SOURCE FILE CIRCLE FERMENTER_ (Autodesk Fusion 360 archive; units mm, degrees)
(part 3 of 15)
sketch "Schizzo24" plane through (0, -88.4, 0) normal (0, 1, 0) x axis (-1, 0, 0)
  line L1 (-140.6, 91.5) -> (-140.6, -63.5)
  line L2 (-150.8209, 91.5) -> (-140.6, 91.5)
  line L3 (-150.8209, 41.5) -> (-150.8209, 91.5)
  line L4 (-150.8209, -13.5) -> (-150.8209, 41.5)
  line L5 (-150.8209, -13.5) -> (-150.8209, -63.5)
  line L6 (-140.6, -63.5) -> (-150.8209, -63.5)
  line L7 (-160, -63.5) -> (-85, -63.5)
  line L8 (-160, 91.5) -> (-160, -63.5)
  line L9 (-85, 91.5) -> (-160, 91.5)
  line L10 (0, 91.5) -> (-85, 91.5)
  line L11 (0, 81.5) -> (0, 91.5)
  line L12 (-95, 81.5) -> (0, 81.5)
  curve K1 (-125, 51.5) -> (-95, 81.5)
  line L13 (-125, -23.5) -> (-125, 51.5)
  curve K2 (-125, -23.5) -> (-95, -53.5)
  line L14 (0, -53.5) -> (-95, -53.5)
  line L15 (0, -63.5) -> (0, -53.5)
  line L16 (-85, -63.5) -> (0, -63.5)
  line L17 (-139, 78.5) -> (-139, -14.5)
  circle C1 centre (-139, 76) radius 1.5
  circle C2 centre (-139, 68) radius 1.5
  circle C3 centre (-139, 68) radius 2.5
  circle C4 centre (-139, 76) radius 2.5
  circle C5 centre (-139, -4) radius 1.5
  circle C6 centre (-139, -12) radius 1.5
  circle C7 centre (-139, -4) radius 1.5
  circle C8 centre (-139, -12) radius 1.5
  circle C9 centre (-32, 86.5) radius 3.35
  circle C10 centre (-130, 51.5) radius 3.35
  circle C11 centre (-95, 86.5) radius 3.35
  circle C12 centre (-95, -58.5) radius 3.35
  circle C13 centre (-130, -23.5) radius 3.35
  circle C14 centre (-32, -58.5) radius 3.35
  circle C15 centre (-139, -4) radius 2.5
  circle C16 centre (-139, -12) radius 2.5
  point P36 (-139, -14.5)
  point P37 (-139, 78.5)
  concentric C2 C3
  concentric C1 C4
  concentric C5 C15
  concentric C8 C16
  coincident C16 P36
  coincident C4 P37
  vertical L17
  dimension "d758" diameter C3 = 5
  dimension "d759" diameter C4 = 5
  dimension "d760" diameter C15 = 5
  dimension "d761" diameter C16 = 5
extrude "Estrusione20" add sketch "Schizzo24" profile of L1 C1 C2 C3 C4 C5 C6 C7 C8 C15 C16 L17 to an object
sketch "Schizzo25" plane through (0, -90, 0) normal (0, -1, 0) x axis (1, 0, 0)
  line L1 (160, -63.5) -> (85, -63.5)
  line L2 (160, 91.5) -> (160, -63.5)
  line L3 (85, 91.5) -> (160, 91.5)
  line L4 (0, 91.5) -> (85, 91.5)
  line L5 (0, 81.5) -> (0, 91.5)
  line L6 (95, 81.5) -> (0, 81.5)
  curve K1 (125, 51.5) -> (95, 81.5)
  line L7 (125, -23.5) -> (125, 51.5)
  curve K2 (125, -23.5) -> (95, -53.5)
  line L8 (0, -53.5) -> (95, -53.5)
  line L9 (0, -63.5) -> (0, -53.5)
  line L10 (85, -63.5) -> (0, -63.5)
  curve K3 (139, -2.5) -> (139, -2.5)
  circle C1 centre (139, -4) radius 1.5
  circle C2 centre (139, -12) radius 1.5
  circle C3 centre (32, 86.5) radius 3.35
  circle C4 centre (130, 51.5) radius 3.35
  circle C5 centre (95, 86.5) radius 3.35
  circle C6 centre (95, -58.5) radius 3.35
  circle C7 centre (130, -23.5) radius 3.35
  circle C8 centre (32, -58.5) radius 3.35
  circle C9 centre (139, -12) radius 1.5
extrude "Estrusione21" add sketch "Schizzo25" profile of C1 C2 K3 C9 against normal blind 0.8
work_plane "Piano di lavoro7" AlongDistance -5
sketch "Schizzo26" plane through (0, -85, 0) normal (0, -1, 0) x axis (-1, 0, 0)
  curve K1 (-140.3526, 4.6485) -> (-140.4601, 4.3436)
  circle C1 centre (-139, -76) radius 1.5
  circle C2 centre (-139, -68) radius 1.5
  circle C3 centre (-139, 12) radius 1.5
  circle C4 centre (-139, 4) radius 2.3
  circle C5 centre (-139, 12) radius 2.3
  circle C6 centre (-139, -68) radius 2.3
  circle C7 centre (-139, -76) radius 2.3
  arc A1 centre (-139, 4) radius 1.5 clockwise from (-140.3526, 4.6485) to (-140.4601, 4.3436)
  concentric C3 C5
  concentric C2 C6
  concentric C1 C7
  dimension "d768" diameter C4 = 4.6
  dimension "d769" diameter C5 = 4.6
  dimension "d770" diameter C6 = 4.6
  dimension "d771" diameter C7 = 4.6
extrude "Estrusione22" cut sketch "Schizzo26" profile of C1 C2 C3 C4 C5 C6 C7 against normal blind 5.06
component_insert "Inserimento componente2"
component_insert "Inserimento componente3"
component_insert "Inserimento componente4"
component_insert "Inserimento componente5"
sketch "Schizzo27" plane through (0, -85, 0) normal (0, 1, 0) x axis (-1, 0, 0)
  line L1 (-137.1434, -13.3576) -> (-137.1434, -10.6424)
  line L2 (-137.1434, -5.3576) -> (-137.1434, -2.6424)
  line L3 (-137.1434, 74.6424) -> (-137.1434, 77.3576)
  line L4 (-137.1434, 66.6424) -> (-137.1434, 69.3576)
  arc A1 centre (-139, -12) radius 2.3 clockwise from (-137.1434, -13.3576) to (-137.1434, -10.6424)
  circle C1 centre (-139, -12) radius 1.5
  arc A2 centre (-139, -4) radius 2.3 clockwise from (-137.1434, -5.3576) to (-137.1434, -2.6424)
  circle C2 centre (-139, -4) radius 1.5
  arc A3 centre (-139, 76) radius 2.3 clockwise from (-137.1434, 74.6424) to (-137.1434, 77.3576)
  circle C3 centre (-139, 76) radius 1.5
  arc A4 centre (-139, 68) radius 2.3 clockwise from (-137.1434, 66.6424) to (-137.1434, 69.3576)
  circle C4 centre (-139, 68) radius 1.5
  circle C5 centre (-139, 68) radius 2
  circle C6 centre (-139, 76) radius 2
  circle C7 centre (-139, -4) radius 2
  circle C8 centre (-139, -12) radius 2
  concentric A4 C5
  concentric A3 C6
  concentric A2 C7
  concentric A1 C8
  dimension "d792" diameter C5 = 4
  dimension "d793" diameter C6 = 4
  dimension "d794" diameter C7 = 4
  dimension "d795" diameter C8 = 4
extrude "Estrusione24" cut sketch "Schizzo27" profile of L1 C1 L2 C2 L3 C3 L4 C4 C5 C6 C7 C8 against normal blind 4.2
joint "Assembla2" alignAngle 0 alignOffsetX 0 alignOffsetY 0 alignOffsetZ 0
joint "Assembla3" alignAngle 0 alignOffsetX 0 alignOffsetY 0 alignOffsetZ 0
joint "Assembla4" alignAngle 0 alignOffsetX 0 alignOffsetY 0 alignOffsetZ 0
joint "Assembla5" alignAngle 0 alignOffsetX 0 alignOffsetY 0 alignOffsetZ 0
sketch "Schizzo2" plane through (0, -88.4, 0) normal (0, 1, 0) x axis (-1, 0, 0)
  line L1 (-140.6, 74.0791) -> (-140.6, 69.9209)
  line L2 (-140.6, 91.5) -> (-140.6, 77.9209)
  line L3 (-150.8209, 91.5) -> (-140.6, 91.5)
  line L4 (-150.8209, 41.5) -> (-150.8209, 91.5)
  line L5 (-150.8209, -13.5) -> (-150.8209, 41.5)
  line L6 (-150.8209, -13.5) -> (-150.8209, -63.5)
  line L7 (-140.6, -63.5) -> (-150.8209, -63.5)
  line L8 (-140.6, -13.9209) -> (-140.6, -63.5)
  line L9 (-140.6, -5.9209) -> (-140.6, -10.0791)
  line L10 (-140.6, 66.0791) -> (-140.6, -2.0791)
  arc A1 centre (-139, 68) radius 2.5 clockwise from (-140.6, 66.0791) to (-140.6, 69.9209)
  arc A2 centre (-139, 76) radius 2.5 clockwise from (-140.6, 74.0791) to (-140.6, 77.9209)
  arc A3 centre (-139, -12) radius 2.5 clockwise from (-140.6, -13.9209) to (-140.6, -10.0791)
  arc A4 centre (-139, -4) radius 2.5 clockwise from (-140.6, -5.9209) to (-140.6, -2.0791)
extrude "Estrusione25" add sketch "Schizzo2" to an object
work_plane "Piano di lavoro1" AlongDistance -25
sketch "Schizzo3" plane through (0, 0, 91.5) normal (0, 0, 1) x axis (1, 0, 0)
  curve K1 (150.8209, -88.4) -> (151.0572, -87.4594)
  curve K2 (151.0572, -87.4594) -> (150.8209, -87.3312)
  line L1 (150.8209, -87.3312) -> (150.8209, -88.4)
extrude "Estrusione26" add sketch "Schizzo3" against normal blind 155
sketch "Schizzo4" plane through (0, -90, 0) normal (0, -1, 0) x axis (1, 0, 0)
  line L1 (160, -63.5) -> (85, -63.5)
  line L2 (160, 91.5) -> (160, -63.5)
  line L3 (85, 91.5) -> (160, 91.5)
  line L4 (0, 91.5) -> (85, 91.5)
  line L5 (0, 81.5) -> (0, 91.5)
  line L6 (95, 81.5) -> (0, 81.5)
  curve K1 (125, 51.5) -> (95, 81.5)
  line L7 (125, -23.5) -> (125, 51.5)
  curve K2 (125, -23.5) -> (95, -53.5)
  line L8 (0, -53.5) -> (95, -53.5)
  line L9 (0, -63.5) -> (0, -53.5)
  line L10 (85, -63.5) -> (0, -63.5)
  line L11 (139.6, 91.5) -> (139.6, 78.4269)
  line L12 (140.6, 91.5) -> (139.6, 91.5)
  line L13 (140.6, 77.9209) -> (140.6, 91.5)
  line L14 (139.6, 73.5731) -> (139.6, 70.4269)
  line L15 (140.6, 69.9209) -> (140.6, 74.0791)
  line L16 (140.6, -2.0791) -> (140.6, 66.0791)
  line L17 (139.6, 65.5731) -> (139.6, -1.5731)
  line L18 (140.6, -10.0791) -> (140.6, -5.9209)
  line L19 (139.6, -6.4269) -> (139.6, -9.5731)
  line L20 (140.6, -63.5) -> (140.6, -13.9209)
  line L21 (139.6, -63.5) -> (140.6, -63.5)
  line L22 (139.6, -14.4269) -> (139.6, -63.5)
  circle C1 centre (32, -58.5) radius 3.35
  circle C2 centre (130, -23.5) radius 3.35
  circle C3 centre (95, -58.5) radius 3.35
  circle C4 centre (95, 86.5) radius 3.35
  circle C5 centre (130, 51.5) radius 3.35
  circle C6 centre (32, 86.5) radius 3.35
  arc A1 centre (139, 76) radius 2.5 clockwise from (139.6, 78.4269) to (140.6, 77.9209)
  arc A2 centre (139, 68) radius 2.5 clockwise from (139.6, 70.4269) to (140.6, 69.9209)
  arc A3 centre (139, 76) radius 2.5 clockwise from (140.6, 74.0791) to (139.6, 73.5731)
  arc A4 centre (139, 68) radius 2.5 clockwise from (140.6, 66.0791) to (139.6, 65.5731)
  arc A5 centre (139, -4) radius 2.5 clockwise from (139.6, -1.5731) to (140.6, -2.0791)
  arc A6 centre (139, -4) radius 2.5 clockwise from (140.6, -5.9209) to (139.6, -6.4269)
  arc A7 centre (139, -12) radius 2.5 clockwise from (139.6, -9.5731) to (140.6, -10.0791)
  arc A8 centre (139, -12) radius 2.5 clockwise from (140.6, -13.9209) to (139.6, -14.4269)
extrude "Estrusione27" add sketch "Schizzo4" profile of L1 L3 A1 L11 L12 L13 A2 L14 A3 L15 A4 L16 A5 L17 A6 L18 A7 L19 A8 L20 L21 L22 against normal blind 7
mirror "Specchio2" mirrorStitchTolerance 0.1
mirror "Specchio2" mirrorStitchTolerance 0.1
component_from_bodies "Corpo->Comp1"
base_feature "Lavorazione di base1"
sketch "Schizzo2" plane through (0, 88.4, 0) normal (0, -1, 0) x axis (1, 0, 0)
  line L1 (0, -53.5) -> (95, -53.5)
  line L2 (0, -63.5) -> (0, -53.5)
  line L3 (95, -63.5) -> (0, -63.5)
  curve K1 (95, -63.5) -> (135, -23.5)
  line L4 (135, 51.5) -> (135, -23.5)
  curve K2 (95, 91.5) -> (135, 51.5)
  line L5 (0, 91.5) -> (95, 91.5)
  line L6 (0, 81.5) -> (0, 91.5)
  line L7 (95, 81.5) -> (0, 81.5)
  curve K3 (125, 51.5) -> (95, 81.5)
  line L8 (125, -23.5) -> (125, 51.5)
  curve K4 (125, -23.5) -> (95, -53.5)
  line L9 (95, -63) -> (0, -63)
  curve K5 (95, -63) -> (134.5, -23.5)
  line L10 (134.5, 51.5) -> (134.5, -23.5)
  line L11 (0, 91) -> (0, -63)
  curve K6 (95, 91) -> (134.5, 51.5)
  line L12 (0, 91) -> (95, 91)
  circle C1 centre (32, 86.5) radius 1.75
  circle C2 centre (130, 51.5) radius 1.75
  circle C3 centre (95, 86.5) radius 1.75
  circle C4 centre (95, -58.5) radius 1.75
  circle C5 centre (130, -23.5) radius 1.75
  circle C6 centre (32, -58.5) radius 1.75
  point P26 (0, 91)
  coincident L6 P26
  perpendicular L9 L11
  dimension "d782" = -0.5
  dimension "d785" = -0.5
extrude "Estrusione2" new body sketch "Schizzo2" profile of C1 C2 C3 C4 C5 C6 L1 L2 L6 L7 K3 L8 K4 K5 L9 L10 L11 L12 K6 along normal blind 3
component_from_bodies "Corpo->Comp2"
copy_paste "CopiaIncolla2"
joint "Assembla2" alignAngle 0 alignOffsetX 0 alignOffsetY 0 alignOffsetZ 0
remove_instance "RimuoviIstanza1"
component_from_bodies "Corpo->Comp1"
base_feature "Lavorazione di base1" bodies "PROFILO BASE"
mirror "Specchio1" mirrorStitchTolerance 0.1
mirror "Specchio1" mirrorStitchTolerance 0.1
remove_instance "RimuoviIstanza2"
remove_instance "RimuoviIstanza4"
mirror_component "SpecchiaComponente1"
derived_instance "DerivedInstance1"
mirror_component "SpecchiaComponente2"
derived_instance "DerivedInstance2"
mirror "Specchio1" mirrorStitchTolerance 0.1
mirror_component "SpecchiaComponente3"
derived_instance "DerivedInstance3"
derived_instance "DerivedInstance4"
derived_instance "DerivedInstance5"
derived_instance "DerivedInstance6"
sketch "Schizzo1" plane through (0, -72.4, 0) normal (0, 1, 0) x axis (-1, 0, 0)
  line L1 (142, 64) -> (-142, 64)
  curve K1 (142, 64) -> (143, 65)
  line L2 (143, 79) -> (143, 65)
  curve K2 (143, 79) -> (142, 80)
  line L3 (-142, 80) -> (142, 80)
  curve K3 (-143, 79) -> (-142, 80)
  line L4 (-143, 65) -> (-143, 79)
  curve K4 (-142, 64) -> (-143, 65)
  line L5 (142, 64) -> (-142, 64)
  curve K5 (142, 64) -> (143, 65)
  line L6 (143, 79) -> (143, 65)
  curve K6 (143, 79) -> (142, 80)
  line L7 (-142, 80) -> (142, 80)
  curve K7 (-143, 79) -> (-142, 80)
  line L8 (-143, 65) -> (-143, 79)
  curve K8 (-142, 64) -> (-143, 65)
  circle C1 centre (139, 76) radius 1.75
  circle C2 centre (139, 68) radius 1.75
  circle C3 centre (-139, 68) radius 1.75
  circle C4 centre (-139, 76) radius 1.75
  circle C5 centre (139, 76) radius 1.75
  circle C6 centre (139, 68) radius 1.75
  circle C7 centre (-139, 68) radius 1.75
  circle C8 centre (-139, 76) radius 1.75
joint "Assembla4" alignAngle 0 alignOffsetX 0 alignOffsetY 0 alignOffsetZ 0
sketch "Schizzo1" plane through (0, 0, -88.5) normal (0, 0, -1) x axis (1, 0, 0)
  line L1 (95, 55) -> (0, 55)
  curve K1 (95, 55) -> (125, 25)
  line L2 (125, -25) -> (125, 25)
  curve K2 (95, -55) -> (125, -25)
  line L3 (0, -55) -> (95, -55)
  line L4 (0, -65) -> (0, -55)
  line L5 (85, -65) -> (0, -65)
  line L6 (160, -65) -> (85, -65)
  line L7 (160, 65) -> (160, -65)
  line L8 (85, 65) -> (160, 65)
  line L9 (0, 65) -> (85, 65)
  line L10 (0, 55) -> (0, 65)
  curve K3 (95, -55) -> (125, -25)
  line L11 (95, -55) -> (0, -55)
  line L12 (125, -25) -> (125, 25)
  line L13 (135, -25) -> (135, 0)
  curve K4 (95, -65) -> (135, -25)
  line L14 (95, -65) -> (0, -65)
  line L15 (135, 0) -> (125, 0)
  line L16 (122, -25) -> (122, 0)
  curve K5 (95, -52) -> (122, -25)
  line L17 (95, -52) -> (0, -52)
  line L18 (122, 0) -> (125, 0)
  line L19 (0, -52) -> (0, -65)
  circle C1 centre (32, -60) radius 3.35
  circle C2 centre (130, -25) radius 3.35
  circle C3 centre (95, -60) radius 3.35
  circle C4 centre (95, 60) radius 3.35
  circle C5 centre (130, 25) radius 3.35
  circle C6 centre (32, 60) radius 3.35
  circle C7 centre (130, -25) radius 1.75
  circle C8 centre (95, -60) radius 1.75
  circle C9 centre (32, -60) radius 1.75
  point P27 (125, 0)
  point P14 (0, -65)
  point P33 (0, -65)
  midpoint L2 P27
  perpendicular L13 L15
  perpendicular L16 L18
  coincident P14 P33
  perpendicular L17 L19
extrude "Estrusione1" new body sketch "Schizzo1" profile of C1 C2 C3 L2 K2 L3 L4 L5 L6 K3 L11 L12 L13 K4 L14 L15 L16 K5 L17 L18 L19 C7 C8 C9 along normal blind 15
sketch "Schizzo2" plane through (0, 0, 0) normal (0, -1, 0) x axis (1, 0, 0)
  line L1 (122, -88.5) -> (135, -88.5)
  line L2 (122, -103.5) -> (122, -88.5)
  line L3 (135, -103.5) -> (122, -103.5)
  line L4 (135, -88.5) -> (135, -103.5)
  line L5 (124, -88.5) -> (124, -103.5)
  curve K1 (135, -91) -> (135, -88.5)
  curve K2 (129.5, -94.5) -> (135, -91)
  curve K3 (124, -99.2) -> (129.5, -94.5)
  curve K4 (124, -101.7) -> (124, -99.2)
  curve K5 (124, -101.7) -> (135, -88.5)
  line L6 (124, -103.5) -> (124, -101.7)
  point P6 (124, -103.5)
  point P7 (124, -88.5)
  point P8 (135, -91)
  point P10 (124, -99.2)
  point P2 (135, -88.5)
  point P9 (129.5, -94.5)
  point P11 (124, -101.7)
  coincident L3 P6
  coincident L1 P7
  perpendicular L1 L5
  coincident L4 P8
  coincident L5 P10
  vertical K4
  dimension "d828" distance L2 L5 = 2
  dimension "d830" distance P2 P8 = 2.5
  dimension "d831" distance P8 P9 = 3.5
  dimension "d832" distance P9 P10 = 4.7
  dimension "d833" distance L4 P9 = 5.5 (= "d881 / 2")
  dimension "d852" distance P6 P11 = 1.8
  dimension "d853" distance P10 P11 = 2.5
  dimension "d881" distance L4 L5 = 11
sweep "Sweep1" sketch "Schizzo2" TwistAngle 0 TaperAngle 0
sketch "Schizzo3" plane through (0, 0, -88.5) normal (0, 0, 1) x axis (-1, 0, 0)
  line L1 (0, -65) -> (-95, -65)
  line L2 (0, -52) -> (0, -65)
  line L3 (-95, -52) -> (0, -52)
  curve K1 (-95, -52) -> (-122, -25)
  line L4 (-122, 0) -> (-122, -25)
  line L5 (-135, 0) -> (-122, 0)
  line L6 (-135, -25) -> (-135, 0)
  curve K2 (-95, -65) -> (-135, -25)
  line L7 (-95, -54.4) -> (0, -54.4)
  curve K3 (-95, -54.4) -> (-124.4, -25)
  line L8 (-124.4, 0) -> (-124.4, -25)
  line L9 (-122, 0) -> (-124.4, 0)
  line L10 (0, -54.4) -> (0, -52)
  circle C1 centre (-130, -25) radius 1.75
  circle C2 centre (-32, -60) radius 1.75
  circle C3 centre (-95, -60) radius 1.75
  point P10 (-122, 0)
  point P17 (-122, 0)
  point P7 (0, -52)
  point P18 (0, -52)
  coincident P10 P17
  perpendicular L4 L9
  coincident P7 P18
  perpendicular L7 L10
  dimension "d840" = -2.4
extrude "Estrusione2" add sketch "Schizzo3" profile of L2 L3 K1 L4 L5 L8 L7 K3 L9 L10 along normal blind 1.6
extrude "Estrusione4" cut of existing geometry blind -0.2
work_plane "Piano di lavoro1" AlongDistance -1.2
sketch "Schizzo5" plane through (0, 0, -89.7) normal (0, 0, 1) x axis (1, 0, 0)
  curve K1 (95, 61.75) -> (95, 58.25)
  curve K2 (95, 58.25) -> (95, 61.75)
  circle C1 centre (95, 60) radius 1.75
  circle C2 centre (130, 25) radius 3
  circle C3 centre (95, 60) radius 3
  circle C4 centre (32, 60) radius 3
  circle C5 centre (32, 60) radius 1.75
  circle C6 centre (130, 25) radius 1.75
  point P7 (32, 60)
  point P8 (32, 60)
  point P5 (130, 25)
  point P9 (130, 25)
  concentric C1 C3
  coincident P7 P8
  coincident P5 P9
  dimension "d857" diameter C2 = 6
  dimension "d858" diameter C4 = 6 (= "d857")
  dimension "d859" diameter C3 = 6 (= "d857")
extrude "Estrusione5" cut sketch "Schizzo5" profile of K1 K2 C1 C2 C3 C4 C5 against normal blind 16.363
joint "Assembla5" alignAngle 0 alignOffsetX 0 alignOffsetY 0 alignOffsetZ 0
chamfer "Smusso1" distance 1.25
fillet "Raccordo1" radius 0.2
extrude "Estrusione6" cut of existing geometry blind -1.4
sketch "Schizzo6" plane through (0, 0, 0) normal (0, -1, 0) x axis (1, 0, 0)
  line L1 (122, -88.5) -> (135, -88.5)
  line L2 (122, -103.5) -> (122, -88.5)
  line L3 (124, -103.5) -> (122, -103.5)
  line L4 (124, -101.7) -> (124, -103.5)
  curve K1 (135, -88.5) -> (124, -101.7)
  line L5 (122, -101.7) -> (124, -101.7)
  line L6 (124.4, -88.5) -> (122, -88.5)
  curve K2 (124.4, -91.5) -> (124.4, -88.5)
  curve K3 (123.2, -95.1) -> (124.4, -91.5)
  curve K4 (122, -98.7) -> (123.2, -95.1)
  curve K5 (122, -101.7) -> (122, -98.7)
  curve K6 (122, -101.7) -> (124.4, -88.5)
  point P6 (124, -101.7)
  point P7 (124, -101.7)
  point P8 (122, -101.7)
  point P3 (122, -88.5)
  point P9 (122, -88.5)
  point P10 (124.4, -88.5)
  point P13 (122, -98.7)
  point P11 (124.4, -91.5)
  point P12 (123.2, -95.1)
  coincident P6 P7
  coincident L2 P8
  perpendicular L2 L5
  coincident P3 P9
  coincident L1 P10
  vertical K5
  vertical K2
  dimension "d867" distance P9 P10 = 2.4
  dimension "d868" distance P8 P13 = 3
  dimension "d869" distance P10 P11 = 3
  dimension "d870" distance P11 P12 = 3.6 (= "d873 / 2")
  dimension "d873" distance P11 P13 = 7.2
  dimension "d874" distance L2 P12 = 1.2 (= "d867 / 2")
sweep "Sweep2" sketch "Schizzo6" TwistAngle 0 TaperAngle 0
mirror "Specchio1" mirrorStitchTolerance 0.1
mirror "Specchio2" mirrorStitchTolerance 0.1
component_from_bodies "Corpo->Comp1"
component_from_bodies "Corpo->Comp2"
sketch "Schizzo1" plane through (0, 0, 0) normal (-1, 0, 0) x axis (0, -1, 0)
  curve K1 (-52, -101.7) -> (-54.4, -88.5)
  line L1 (-65, -88.5) -> (-54.4, -88.5)
  curve K2 (-54, -101.7) -> (-65, -88.5)
  line L2 (-54, -103.5) -> (-54, -101.7)
  line L3 (-52, -103.5) -> (-54, -103.5)
  line L4 (-52, -101.7) -> (-52, -103.5)
  line L5 (-53, -101.7) -> (-59.7, -88.5)
  line L6 (-59.7, -101.6426) -> (-59.7, -88.5)
  line L7 (-53, -90.6394) -> (-53, -101.7)
  curve K3 (-59.7, -93) -> (-59.7, -88.5)
  curve K4 (-56.35, -95.1) -> (-59.7, -93)
  curve K5 (-53, -97.2) -> (-56.35, -95.1)
  curve K6 (-53, -101.7) -> (-53, -97.2)
  curve K7 (-53, -101.7) -> (-59.7, -88.5)
  line L8 (-54, -101.7) -> (-52, -101.7)
  line L9 (-53, -103.5) -> (-53, -101.7)
  line L10 (-25, -88.5) -> (25, -88.5)
  line L11 (-25, -101.7) -> (-25, -88.5)
  line L12 (25, -101.7) -> (-25, -101.7)
  line L13 (25, -101.7) -> (25, -88.5)
  line L14 (0, -127.2244) -> (0, -88.5)
  line L15 (53, -103.5) -> (53, -101.7)
  curve K8 (53, -101.7) -> (59.7, -88.5)
  curve K9 (59.7, -93) -> (59.7, -88.5)
  curve K10 (56.35, -95.1) -> (59.7, -93)
  curve K11 (53, -97.2) -> (56.35, -95.1)
  curve K12 (53, -101.7) -> (53, -97.2)
  curve K13 (52, -101.7) -> (54.4, -88.5)
  line L16 (52, -103.5) -> (52, -101.7)
  line L17 (54, -103.5) -> (52, -103.5)
  line L18 (54, -101.7) -> (54, -103.5)
  curve K14 (54, -101.7) -> (65, -88.5)
  line L19 (54.4, -88.5) -> (65, -88.5)
  point P8 (-59.7, -88.5)
  point P12 (-59.7, -93)
  point P14 (-53, -97.2)
  point P3 (-52, -101.7)
  point P15 (-52, -101.7)
  point P5 (-54, -101.7)
  point P16 (-54, -101.7)
  point P9 (-53, -101.7)
  point P17 (-53, -103.5)
  point P22 (0, -88.5)
  point P26 (59.7, -88.5)
  point P24 (53, -101.7)
  point P25 (53, -103.5)
  point P13 (-56.35, -95.1)
  midpoint L1 P8
  perpendicular L1 L6
  coincident L6 P12
  coincident L7 P14
  vertical L7
  coincident P3 P15
  coincident P5 P16
  midpoint P9 L8
  midpoint L3 P17
  midpoint L10 P22
  perpendicular L10 L14
  symmetric P8 L14 P26
  symmetric P9 L14 P24
  symmetric K7 L14 K8
  symmetric P17 L14 P25
  dimension "d886" distance P8 P12 = 4.5 (= "d887")
  dimension "d887" distance P9 P14 = 4.5
  dimension "d888" distance P12 P14 = 4.2
  dimension "d889" distance P13 P14 = 2.1 (= "d888 / 2")
  dimension "d890" distance L6 P14 = 6.7
  dimension "d891" distance P12 P13 = 3.35 (= "d890 / 2")
extrude "Estrusione1" cut sketch "Schizzo1" profile of K1 L1 L3 L4 K7 L9 L15 K8 K13 L16 L17 L19 against normal blind 2.2
sketch "Schizzo1" plane through (0, 0, 0) normal (1, 0, 0) x axis (0, 1, 0)
  curve K1 (52, -101.7) -> (54.4, -88.5)
  line L1 (52, -103.5) -> (52, -101.7)
  line L2 (54, -103.5) -> (52, -103.5)
  line L3 (54, -101.7) -> (54, -103.5)
  curve K2 (54, -101.7) -> (65, -88.5)
  line L4 (54.4, -88.5) -> (65, -88.5)
  line L5 (59.7, -88.5) -> (54.4, -88.5)
  curve K3 (59.7, -88.5) -> (53, -101.7)
  line L6 (53, -103.5) -> (53, -101.7)
  line L7 (52, -103.5) -> (53, -103.5)
  line L8 (52, -101.7) -> (52, -103.5)
  curve K4 (52, -101.7) -> (54.4, -88.5)
  curve K5 (-54.4, -88.5) -> (-52, -101.7)
  line L9 (-52, -103.5) -> (-52, -101.7)
  line L10 (-53, -103.5) -> (-52, -103.5)
  line L11 (-53, -101.7) -> (-53, -103.5)
  curve K6 (-53, -101.7) -> (-59.7, -88.5)
  line L12 (-54.4, -88.5) -> (-59.7, -88.5)
extrude "Estrusione1" add sketch "Schizzo1" profile of K1 L1 L2 L4 L5 K3 L6 L7 L8 K4 K5 L9 L10 L11 K6 L12 along normal blind 2
sketch "Schizzo1" plane through (148.4, 0, 0) normal (1, 0, 0) x axis (0, 1, 0)
  curve K1 (-83.9651, 77.4206) -> (-79.9057, 75.4498)
  line L1 (-83.9651, 76.5591) -> (-83.9651, 77.4206)
  curve K2 (-83.9651, 76.5591) -> (-84.564, 75.5072)
  curve K3 (-84.564, 67.4928) -> (-83.9651, 66.4409)
  line L2 (-83.9651, 65.58) -> (-83.9651, 66.4409)
  curve K4 (-79.9058, 67.5505) -> (-83.9651, 65.58)
  curve K5 (-79.9057, 75.4498) -> (-79.9058, 67.5505)
  circle C1 centre (-81.5735, 71.5) radius 0.75
  arc A1 centre (-81.5735, 71.5) radius 5 clockwise from (-84.564, 67.4928) to (-84.564, 75.5072)
  circle C2 centre (-81.5735, -43.5) radius 0.75
  circle C3 centre (-81.5735, 71.5) radius 0.75
  circle C4 centre (81.5735, 71.5) radius 0.75
  circle C5 centre (81.5735, -43.5) radius 0.75
  circle C6 centre (-81.5735, 71.5) radius 2
  circle C7 centre (-81.5735, -43.5) radius 2
  circle C8 centre (81.5735, -43.5) radius 2
  circle C9 centre (81.5735, 71.5) radius 2
  concentric C1 C6
  concentric C2 C7
  concentric C5 C8
  concentric C4 C9
  dimension "d907" diameter C6 = 4
  dimension "d914" diameter C7 = 4
  dimension "d915" diameter C8 = 4
  dimension "d916" diameter C9 = 4
extrude "Estrusione1" cut sketch "Schizzo1" profile of C1 C3 C6 blind -4
component_insert "Inserimento componente1"
joint "Assembla1" alignAngle -90 alignOffsetX 0 alignOffsetY 0 alignOffsetZ 0
extrude "Estrusione2" cut sketch "Schizzo1" profile of C2 C4 C5 C7 C8 C9 blind -4
sketch "Schizzo2" plane through (-160, 0, 0) normal (-1, 0, 0) x axis (0, -1, 0)
  line L1 (-65, 116.5) -> (65, 116.5)
  curve K1 (-65, 116.5) -> (-90, 91.5)
  line L2 (-90, -63.5) -> (-90, 91.5)
  curve K2 (-65, -88.5) -> (-90, -63.5)
  line L3 (65, -88.5) -> (-65, -88.5)
  curve K3 (65, -88.5) -> (90, -63.5)
  line L4 (90, 91.5) -> (90, -63.5)
  curve K4 (65, 116.5) -> (90, 91.5)
  line L5 (65, 114.9) -> (-65, 114.9)
  curve K5 (88.4, 91.5) -> (65, 114.9)
  line L6 (88.4, -63.5) -> (88.4, 91.5)
  curve K6 (88.4, -63.5) -> (65, -86.9)
  line L7 (-65, -86.9) -> (65, -86.9)
  curve K7 (-88.4, -63.5) -> (-65, -86.9)
  line L8 (-88.4, 91.5) -> (-88.4, -63.5)
  curve K8 (-88.4, 91.5) -> (-65, 114.9)
extrude "Estrusione2" new body sketch "Schizzo2" along normal blind 20
work_plane "Piano di lavoro1" AlongDistance -25
sketch "Schizzo3" plane through (0, 0, -63.5) normal (0, 0, -1) x axis (-1, 0, 0)
  curve K1 (160, 88.4) -> (142.5, 81.4)
  line L1 (148.4, 79.5735) -> (148.4, 83.5735)
  line L2 (160, 90) -> (85, 90)
  line L3 (85, 90) -> (160, 90)
  line L4 (0, 90) -> (85, 90)
  line L5 (95, 90) -> (0, 90)
  line L6 (125, 90) -> (95, 90)
  line L7 (125, 90) -> (95, 90)
  line L8 (0, 90) -> (95, 90)
  line L9 (85, 90) -> (0, 90)
  line L10 (35.35, 90) -> (28.65, 90)
  line L11 (133.35, 90) -> (126.65, 90)
  line L12 (98.35, 90) -> (91.65, 90)
  line L13 (91.65, 90) -> (98.35, 90)
  line L14 (126.65, 90) -> (133.35, 90)
  line L15 (28.65, 90) -> (35.35, 90)
  line L16 (148.4, 90) -> (148.4, 77.9)
  curve K2 (160, 86.8) -> (142.5, 79.8)
  line L17 (150, 90) -> (150, 77.9)
  line L18 (149.7497, 77.9) -> (150, 77.9)
  line L19 (148.4, 77.9) -> (149.7497, 77.9)
  line L20 (160, 88.4) -> (160, 86.8)
  point P18 (148.4, 90)
  point P5 (148.4, 79.5735)
  point P3 (160, 88.4)
  point P24 (160, 88.4)
  point P17 (148.4, 77.9)
  coincident L3 P18
  perpendicular L3 L16
  coincident P5 L16
  perpendicular L17 L18
  perpendicular L16 L19
  coincident P3 P24
  perpendicular L19 L20
  dimension "d922" distance P17 P18 = 12.1
  dimension "d923" = 1.6
  dimension "d924" = 1.6
sweep "Sweep1" sketch "Schizzo3" TwistAngle 0 TaperAngle 0
sketch "Schizzo4" plane through (-180, 0, 0) normal (-1, 0, 0) x axis (0, -1, 0)
  line L1 (65, 114.9) -> (-65, 114.9)
  curve K1 (88.4, 91.5) -> (65, 114.9)
  line L2 (88.4, -63.5) -> (88.4, 91.5)
  curve K2 (65, -86.9) -> (88.4, -63.5)
  line L3 (-65, -86.9) -> (65, -86.9)
  curve K3 (-88.4, -63.5) -> (-65, -86.9)
  line L4 (-88.4, 91.5) -> (-88.4, -63.5)
  curve K4 (-65, 114.9) -> (-88.4, 91.5)
  line L5 (90, 91.5) -> (90, -63.5)
  curve K5 (65, 116.5) -> (90, 91.5)
  line L6 (-65, 116.5) -> (65, 116.5)
  curve K6 (-90, 91.5) -> (-65, 116.5)
  line L7 (-90, -63.5) -> (-90, 91.5)
  curve K7 (-65, -88.5) -> (-90, -63.5)
  line L8 (65, -88.5) -> (-65, -88.5)
  curve K8 (90, -63.5) -> (65, -88.5)
  line L9 (-65, -86.4) -> (65, -86.4)
  curve K9 (-87.9, -63.5) -> (-65, -86.4)
  line L10 (-87.9, 91.5) -> (-87.9, -63.5)
  curve K10 (-65, 114.4) -> (-87.9, 91.5)
  line L11 (65, 114.4) -> (-65, 114.4)
  curve K11 (87.9, 91.5) -> (65, 114.4)
  line L12 (87.9, -63.5) -> (87.9, 91.5)
  curve K12 (65, -86.4) -> (87.9, -63.5)
  dimension "d931" = 0.5
extrude "Estrusione3" new body sketch "Schizzo4" profile of L9 K9 K12 L10 K11 L11 K10 L12 against normal blind 3
offset_faces "FacceDiOffset1" distance -0.2
offset_faces "FacceDiOffset1" distance -0.2
sketch "Schizzo1" plane through (158, 0, 0) normal (1, 0, 0) x axis (0, 1, 0)
  line L1 (86.7, 91.3) -> (86.7, -63.3)
  line L2 (82.7, 91.3) -> (86.7, 91.3)
  curve K1 (64.8, 109.2) -> (82.7, 91.3)
  line L3 (64.8, 113.2) -> (64.8, 109.2)
  line L4 (-64.8, 113.2) -> (64.8, 113.2)
  line L5 (-64.8, 109.2) -> (-64.8, 113.2)
  curve K2 (-82.7, 91.3) -> (-64.8, 109.2)
  line L6 (-86.7, 91.3) -> (-82.7, 91.3)
  line L7 (-86.7, -63.3) -> (-86.7, 91.3)
  line L8 (-82.7, -63.3) -> (-86.7, -63.3)
  curve K3 (-64.8, -81.2) -> (-82.7, -63.3)
  line L9 (-64.8, -85.2) -> (-64.8, -81.2)
  line L10 (64.8, -85.2) -> (-64.8, -85.2)
  line L11 (64.8, -81.2) -> (64.8, -85.2)
  curve K4 (82.7, -63.3) -> (64.8, -81.2)
  line L12 (86.7, -63.3) -> (82.7, -63.3)
  circle C1 centre (81.5735, 14) radius 1.75
  circle C2 centre (-81.5735, 14) radius 1.75
  circle C3 centre (-81.5735, 71.5) radius 1.75
  circle C4 centre (-45, 108.0735) radius 1.75
  circle C5 centre (45, 108.0735) radius 1.75
  circle C6 centre (81.5735, 71.5) radius 1.75
  circle C7 centre (0, 108.0735) radius 1.75
  circle C8 centre (0, -80.0735) radius 1.75
  circle C9 centre (81.5735, -43.5) radius 1.75
  circle C10 centre (45, -80.0735) radius 1.75
  circle C11 centre (-45, -80.0735) radius 1.75
  circle C12 centre (-81.5735, -43.5) radius 1.75
offset_faces "FacceDiOffset1" distance -0.2
offset_faces "FacceDiOffset2" distance -0.2
offset_faces "FacceDiOffset3" distance -0.2
offset_faces "FacceDiOffset4" distance -0.2
remove_instance "RimuoviIstanza2"
extrude "Estrusione3" add of existing geometry blind 1.8
extrude "Estrusione4" add of existing geometry blind 0.4
component_from_bodies "Corpo->Comp1"
sketch "Schizzo1" plane through (-148.4, 0, 0) normal (1, 0, 0) x axis (0, 1, 0)
  line L1 (82.0401, -63.5) -> (82.0401, 91.5)
  curve K1 (82.0401, -63.5) -> (65, -80.5401)
  line L2 (-65, -80.5401) -> (65, -80.5401)
  curve K2 (-65, -80.5401) -> (-82.0401, -63.5)
  line L3 (-82.0401, 91.5) -> (-82.0401, -63.5)
  curve K3 (-82.0401, 91.5) -> (-65, 108.5401)
  line L4 (65, 108.5401) -> (-65, 108.5401)
  curve K4 (65, 108.5401) -> (82.0401, 91.5)
  curve K5 (65, 110.4651) -> (83.9651, 91.5)
  line L5 (-65, 110.4651) -> (65, 110.4651)
  curve K6 (-83.9651, 91.5) -> (-65, 110.4651)
  line L6 (-83.9651, -63.5) -> (-83.9651, 91.5)
  curve K7 (-65, -82.4651) -> (-83.9651, -63.5)
  line L7 (65, -82.4651) -> (-65, -82.4651)
  curve K8 (83.9651, -63.5) -> (65, -82.4651)
  line L8 (83.9651, 91.5) -> (83.9651, -63.5)
  line L9 (77.9, -63.5) -> (77.9, 91.5)
  curve K9 (65, -76.4) -> (77.9, -63.5)
  line L10 (-65, -76.4) -> (65, -76.4)
  curve K10 (-65, -76.4) -> (-77.9, -63.5)
  line L11 (-77.9, 91.5) -> (-77.9, -63.5)
  curve K11 (-65, 104.4) -> (-77.9, 91.5)
  line L12 (65, 104.4) -> (-65, 104.4)
  curve K12 (65, 104.4) -> (77.9, 91.5)
  line L13 (86.9365, 91.3) -> (86.9365, -63.3)
  line L14 (82.7, 91.3) -> (86.9365, 91.3)
  curve K13 (82.7, 91.3) -> (64.8, 109.2)
  line L15 (64.8, 113.4365) -> (64.8, 109.2)
  line L16 (-64.8, 113.4365) -> (64.8, 113.4365)
  line L17 (-64.8, 109.2) -> (-64.8, 113.4365)
  curve K14 (-64.8, 109.2) -> (-82.7, 91.3)
  line L18 (-86.9365, 91.3) -> (-82.7, 91.3)
  line L19 (-86.9365, -63.3) -> (-86.9365, 91.3)
  line L20 (-82.7, -63.3) -> (-86.9365, -63.3)
  curve K15 (-82.7, -63.3) -> (-64.8, -81.2)
  line L21 (-64.8, -85.4365) -> (-64.8, -81.2)
  line L22 (64.8, -85.4365) -> (-64.8, -85.4365)
  line L23 (64.8, -81.2) -> (64.8, -85.4365)
  curve K16 (64.8, -81.2) -> (82.7, -63.3)
  line L24 (86.9365, -63.3) -> (82.7, -63.3)
  line L25 (65, 103) -> (-65, 103)
  curve K17 (65, 103) -> (76.5, 91.5)
  line L26 (76.5, -63.5) -> (76.5, 91.5)
  curve K18 (65, -75) -> (76.5, -63.5)
  line L27 (-65, -75) -> (65, -75)
  curve K19 (-65, -75) -> (-76.5, -63.5)
  line L28 (-76.5, 91.5) -> (-76.5, -63.5)
  curve K20 (-65, 103) -> (-76.5, 91.5)
  circle C1 centre (81.5735, 14) radius 1.75
  circle C2 centre (-81.5735, 14) radius 1.75
  circle C3 centre (-81.5735, 71.5) radius 1.75
  circle C4 centre (-45, 108.0735) radius 1.75
  circle C5 centre (45, 108.0735) radius 1.75
  circle C6 centre (81.5735, 71.5) radius 1.75
  circle C7 centre (0, 108.0735) radius 1.75
  circle C8 centre (0, -80.0735) radius 1.75
  circle C9 centre (81.5735, -43.5) radius 1.75
  circle C10 centre (45, -80.0735) radius 1.75
  circle C11 centre (-45, -80.0735) radius 1.75
  circle C12 centre (-81.5735, -43.5) radius 1.75
  dimension "d979" = 1.4
extrude "Estrusione1" add sketch "Schizzo1" profile of L1 K1 L2 K2 L3 K3 L4 K4 K5 L5 K6 L6 K7 L7 K8 L8 L9 K9 L10 K10 L11 K11 L12 K12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 against normal blind 2.4
sketch "Schizzo5" plane through (-150.8, 0, 0) normal (-1, 0, 0) x axis (0, -1, 0)
  line L1 (-65, -82.1107) -> (65, -82.1107)
  curve K1 (65, -82.1107) -> (83.6107, -63.5)
  line L2 (83.6107, -63.5) -> (83.6107, 91.5)
  curve K2 (83.6107, 91.5) -> (65, 110.1107)
  line L3 (65, 110.1107) -> (-65, 110.1107)
  curve K3 (-65, 110.1107) -> (-83.6107, 91.5)
  line L4 (-83.6107, 91.5) -> (-83.6107, -63.5)
  curve K4 (-83.6107, -63.5) -> (-65, -82.1107)
  line L5 (-65, -81.6107) -> (65, -81.6107)
  curve K5 (-83.1107, -63.5) -> (-65, -81.6107)
  line L6 (-83.1107, 91.5) -> (-83.1107, -63.5)
  curve K6 (-65, 109.6107) -> (-83.1107, 91.5)
  line L7 (65, 109.6107) -> (-65, 109.6107)
  curve K7 (83.1107, 91.5) -> (65, 109.6107)
  line L8 (83.1107, -63.5) -> (83.1107, 91.5)
  curve K8 (65, -81.6107) -> (83.1107, -63.5)
  curve K9 (65, -75) -> (76.5, -63.5)
  line L9 (-65, -75) -> (65, -75)
  curve K10 (-76.5, -63.5) -> (-65, -75)
  line L10 (-76.5, 91.5) -> (-76.5, -63.5)
  curve K11 (-65, 103) -> (-76.5, 91.5)
  line L11 (65, 103) -> (-65, 103)
  curve K12 (76.5, 91.5) -> (65, 103)
  line L12 (76.5, -63.5) -> (76.5, 91.5)
  dimension "d951" = 0.5
extrude "Estrusione4" new body sketch "Schizzo5" profile of K5 L5 L8 L6 L7 K6 K7 K8 along normal blind 3
sketch "Schizzo2" plane through (-153.8, 0, 0) normal (-1, 0, 0) x axis (0, -1, 0)
  line L1 (83.1107, 91.5) -> (83.1107, -63.5)
  curve K1 (65, 109.6107) -> (83.1107, 91.5)
  line L2 (-65, 109.6107) -> (65, 109.6107)
  curve K2 (-83.1107, 91.5) -> (-65, 109.6107)
  line L3 (-83.1107, -63.5) -> (-83.1107, 91.5)
  curve K3 (-65, -81.6107) -> (-83.1107, -63.5)
  line L4 (65, -81.6107) -> (-65, -81.6107)
  curve K4 (83.1107, -63.5) -> (65, -81.6107)
  curve K5 (65, 110.1107) -> (83.6107, 91.5)
  line L5 (-65, 110.1107) -> (65, 110.1107)
  curve K6 (-83.6107, 91.5) -> (-65, 110.1107)
  line L6 (-83.6107, -63.5) -> (-83.6107, 91.5)
  curve K7 (-65, -82.1107) -> (-83.6107, -63.5)
  line L7 (65, -82.1107) -> (-65, -82.1107)
  curve K8 (83.6107, -63.5) -> (65, -82.1107)
  line L8 (83.6107, 91.5) -> (83.6107, -63.5)
  curve K9 (65, 112.6107) -> (86.1107, 91.5)
  line L9 (-65, 112.6107) -> (65, 112.6107)
  curve K10 (-86.1107, 91.5) -> (-65, 112.6107)
  line L10 (-86.1107, -63.5) -> (-86.1107, 91.5)
  curve K11 (-65, -84.6107) -> (-86.1107, -63.5)
  line L11 (65, -84.6107) -> (-65, -84.6107)
  curve K12 (86.1107, -63.5) -> (65, -84.6107)
  line L12 (86.1107, 91.5) -> (86.1107, -63.5)
  dimension "d954" = 0.5
  dimension "d955" = 3
extrude "Estrusione2" add sketch "Schizzo2" profile of K5 L8 K6 L5 L6 K8 K7 L7 K9 L12 K10 L9 L10 K12 K11 L11 to an object
sketch "Schizzo3" plane through (-148.4, 0, 0) normal (1, 0, 0) x axis (0, 1, 0)
  curve K1 (65, 110.4651) -> (83.9651, 91.5)
  line L1 (-65, 110.4651) -> (65, 110.4651)
  curve K2 (-83.9651, 91.5) -> (-65, 110.4651)
  line L2 (-83.9651, -63.5) -> (-83.9651, 91.5)
  curve K3 (-65, -82.4651) -> (-83.9651, -63.5)
  line L3 (65, -82.4651) -> (-65, -82.4651)
  curve K4 (83.9651, -63.5) -> (65, -82.4651)
  line L4 (83.9651, 91.5) -> (83.9651, -63.5)
  curve K5 (-76.5, -63.5) -> (-65, -75)
  line L5 (-76.5, 91.5) -> (-76.5, -63.5)
  curve K6 (-65, 103) -> (-76.5, 91.5)
  line L6 (65, 103) -> (-65, 103)
  curve K7 (76.5, 91.5) -> (65, 103)
  line L7 (76.5, -63.5) -> (76.5, 91.5)
  curve K8 (65, -75) -> (76.5, -63.5)
  line L8 (-65, -75) -> (65, -75)
  circle C1 centre (-81.5735, -43.5) radius 2
  circle C2 centre (-81.5735, 71.5) radius 2
  circle C3 centre (81.5735, 71.5) radius 2
  circle C4 centre (81.5735, -43.5) radius 2
  circle C5 centre (-81.5735, -43.5) radius 1.75
  circle C6 centre (-81.5735, 71.5) radius 1.75
  circle C7 centre (81.5735, 71.5) radius 1.75
  circle C8 centre (81.5735, -43.5) radius 1.75
  concentric C1 C5
  concentric C2 C6
  concentric C3 C7
  concentric C4 C8
  dimension "d958" diameter C5 = 3.5
  dimension "d959" diameter C6 = 3.5
  dimension "d960" diameter C7 = 3.5
  dimension "d961" diameter C8 = 3.5
extrude "Estrusione5" cut sketch "Schizzo3" profile of C5 C6 C7 C8 against normal blind 51.149
component_from_bodies "Corpo->Comp2"
fillet "Raccordo1" radius 0.5
sketch "Schizzo4" plane through (-148.4, 0, 0) normal (1, 0, 0) x axis (0, 1, 0)
  curve K1 (65, 110.4651) -> (83.9651, 91.5)
  line L1 (-65, 110.4651) -> (65, 110.4651)
  curve K2 (-83.9651, 91.5) -> (-65, 110.4651)
  line L2 (-83.9651, -63.5) -> (-83.9651, 91.5)
  curve K3 (-65, -82.4651) -> (-83.9651, -63.5)
  line L3 (65, -82.4651) -> (-65, -82.4651)
  curve K4 (83.9651, -63.5) -> (65, -82.4651)
  line L4 (83.9651, 91.5) -> (83.9651, -63.5)
  line L5 (-64.3, -78.7) -> (64.3, -78.7)
  curve K5 (-80.2, -62.8) -> (-64.3, -78.7)
  line L6 (-80.2, 90.8) -> (-80.2, -62.8)
  curve K6 (-64.3, 106.7) -> (-80.2, 90.8)
  line L7 (64.3, 106.7) -> (-64.3, 106.7)
  curve K7 (80.2, 90.8) -> (64.3, 106.7)
  line L8 (80.2, -62.8) -> (80.2, 90.8)
  curve K8 (64.3, -78.7) -> (80.2, -62.8)
  curve K9 (-76.5, -63.5) -> (-65, -75)
  line L9 (-76.5, 91.5) -> (-76.5, -63.5)
  curve K10 (-65, 103) -> (-76.5, 91.5)
  line L10 (65, 103) -> (-65, 103)
  curve K11 (76.5, 91.5) -> (65, 103)
  line L11 (76.5, -63.5) -> (76.5, 91.5)
  curve K12 (65, -75) -> (76.5, -63.5)
  line L12 (-65, -75) -> (65, -75)
  circle C1 centre (-81.5735, 71.5) radius 1.75
  circle C2 centre (81.5735, 71.5) radius 1.75
  circle C3 centre (-81.5735, -43.5) radius 1.75
  circle C4 centre (81.5735, -43.5) radius 1.75
  circle C5 centre (0, 108.0735) radius 1.1933
  circle C6 centre (45, 108.0735) radius 1.1933
  circle C7 centre (81.5735, 71.5) radius 1.1933
  circle C8 centre (81.5735, 14) radius 1.1933
  point P26 (80.2, 71.5)
  point P27 (44.1, 106.7)
  point P28 (0, 106.7)
  point P29 (80.2, 14)
  coincident L8 P26
  coincident L7 P27
  midpoint L7 P28
  midpoint L8 P29
  dimension "d980" distance L7 L10 = 3.7
  dimension "d981" distance L8 L11 = 3.7 (= "d980")
  dimension "d982" distance L6 L9 = 3.7 (= "d980")
  dimension "d983" distance L5 L12 = 3.7 (= "d981")
hole "Foratura1" HoleDepth 100 HoleDiameter 3.5 TipAngle 118 CSDiameter 6.7 CSAngle 90
mirror "Specchio1" mirrorStitchTolerance 0.1
work_plane "Piano di lavoro1"
mirror "Specchio2" mirrorStitchTolerance 0.1
sketch "Schizzo1" plane through (-153.8, 0, 0) normal (-1, 0, 0) x axis (0, -1, 0)
  line L1 (-83.1107, -63.5) -> (-83.1107, -45.4967)
  curve K1 (-65, -81.6107) -> (-83.1107, -63.5)
  line L2 (65, -81.6107) -> (-65, -81.6107)
  curve K2 (83.1107, -63.5) -> (65, -81.6107)
  line L3 (83.1107, -45.4967) -> (83.1107, -63.5)
  line L4 (83.1107, 69.5033) -> (83.1107, -41.5033)
  line L5 (83.1107, 91.5) -> (83.1107, 73.4967)
  curve K3 (65, 109.6107) -> (83.1107, 91.5)
  line L6 (-65, 109.6107) -> (65, 109.6107)
  curve K4 (-83.1107, 91.5) -> (-65, 109.6107)
  line L7 (-83.1107, 73.4967) -> (-83.1107, 91.5)
  line L8 (-83.1107, -41.5033) -> (-83.1107, 69.5033)
  line L9 (-83.1107, 14) -> (83.1107, 14)
  line L10 (0, 109.6107) -> (0, -81.6107)
  line L11 (42.5, -33.5) -> (-42.5, -33.5)
  line L12 (42.5, 61.5) -> (42.5, -33.5)
  line L13 (-42.5, 61.5) -> (42.5, 61.5)
  line L14 (-42.5, -33.5) -> (-42.5, 61.5)
  line L15 (42.5, 61.5) -> (-42.5, -33.5)
  line L16 (-42.5, 61.5) -> (42.5, -33.5)
  circle C1 centre (44.1, -78.7) radius 1.75
  circle C2 centre (-44.1, -78.7) radius 1.75
  circle C3 centre (0, -78.7) radius 1.75
  circle C4 centre (44.1, 106.7) radius 1.75
  circle C5 centre (80.2, 14) radius 1.75
  circle C6 centre (-44.1, 106.7) radius 1.75
  circle C7 centre (0, 106.7) radius 1.75
  circle C8 centre (-80.2, 14) radius 1.75
  arc A1 centre (-82.6107, -41.5033) radius 0.5 clockwise from (-82.3802, -41.947) to (-83.1107, -41.5033)
  arc A2 centre (-81.5735, -43.5) radius 1.75 clockwise from (-82.3802, -41.947) to (-82.3802, -45.053)
  arc A3 centre (-82.6107, -45.4967) radius 0.5 clockwise from (-83.1107, -45.4967) to (-82.3802, -45.053)
  arc A4 centre (82.6107, -45.4967) radius 0.5 clockwise from (82.3802, -45.053) to (83.1107, -45.4967)
  arc A5 centre (81.5735, -43.5) radius 1.75 clockwise from (82.3802, -45.053) to (82.3802, -41.947)
  arc A6 centre (82.6107, -41.5033) radius 0.5 clockwise from (83.1107, -41.5033) to (82.3802, -41.947)
  arc A7 centre (82.6107, 69.5033) radius 0.5 clockwise from (82.3802, 69.947) to (83.1107, 69.5033)
  arc A8 centre (81.5735, 71.5) radius 1.75 clockwise from (82.3802, 69.947) to (82.3802, 73.053)
  arc A9 centre (82.6107, 73.4967) radius 0.5 clockwise from (83.1107, 73.4967) to (82.3802, 73.053)
  arc A10 centre (-82.6107, 73.4967) radius 0.5 clockwise from (-82.3802, 73.053) to (-83.1107, 73.4967)
  arc A11 centre (-81.5735, 71.5) radius 1.75 clockwise from (-82.3802, 73.053) to (-82.3802, 69.947)
  arc A12 centre (-82.6107, 69.5033) radius 0.5 clockwise from (-83.1107, 69.5033) to (-82.3802, 69.947)
  point P46 (83.1107, 14)
  point P47 (-83.1107, 14)
  point P48 (0, -81.6107)
  point P49 (0, 109.6107)
  point P54 (0, 14)
  point P52 (42.5, 61.5)
  point P53 (-42.5, 61.5)
  point P50 (-42.5, -33.5)
  midpoint L4 P46
  midpoint L8 P47
  midpoint L2 P48
  midpoint L6 P49
  horizontal L11
  perpendicular L11 L12
  parallel L11 L13
  parallel L12 L14
  coincident L15 P54
  coincident L16 P54
  midpoint L9 P54
  dimension "d992" distance P52 P53 = 85
  dimension "d993" distance P50 P53 = 95
component_insert "Inserimento componente1"
joint "Assembla2" alignAngle 90 alignOffsetX 0 alignOffsetY 0 alignOffsetZ 0
sketch "Schizzo2" plane through (-150.8, 0, 0) normal (1, 0, 0) x axis (0, 1, 0)
  line L1 (83.1107, 69.5033) -> (83.1107, -41.5033)
  line L2 (83.1107, 91.5) -> (83.1107, 73.4967)
  curve K1 (65, 109.6107) -> (83.1107, 91.5)
  line L3 (-65, 109.6107) -> (65, 109.6107)
  curve K2 (-83.1107, 91.5) -> (-65, 109.6107)
  line L4 (-83.1107, 73.4967) -> (-83.1107, 91.5)
  line L5 (-83.1107, -41.5033) -> (-83.1107, 69.5033)
  line L6 (-83.1107, -63.5) -> (-83.1107, -45.4967)
  curve K3 (-65, -81.6107) -> (-83.1107, -63.5)
  line L7 (65, -81.6107) -> (-65, -81.6107)
  curve K4 (83.1107, -63.5) -> (65, -81.6107)
  line L8 (83.1107, -45.4967) -> (83.1107, -63.5)
  line L9 (-10, 22.5) -> (10, 22.5)
  line L10 (10, 47.5) -> (-10, 47.5)
  line L11 (20, 10.5) -> (20, -9)
  line L12 (-20, 10.5) -> (20, 10.5)
  line L13 (-20, -28.5) -> (-20, -9)
  line L14 (20, -28.5) -> (-20, -28.5)
  line L15 (20, 22.5) -> (-20, 22.5)
  line L16 (-20, 47.5) -> (20, 47.5)
  line L17 (20, 35) -> (-20, 35)
  circle C1 centre (-44.1, -78.7) radius 1.75
  circle C2 centre (44.1, -78.7) radius 1.75
  circle C3 centre (0, -78.7) radius 1.75
  circle C4 centre (-44.1, 106.7) radius 1.75
  circle C5 centre (-80.2, 14) radius 1.75
  circle C6 centre (44.1, 106.7) radius 1.75
  circle C7 centre (0, 106.7) radius 1.75
  circle C8 centre (80.2, 14) radius 1.75
  arc A1 centre (82.6107, -41.5033) radius 0.5 clockwise from (83.1107, -41.5033) to (82.3802, -41.947)
  arc A2 centre (82.6107, 69.5033) radius 0.5 clockwise from (82.3802, 69.947) to (83.1107, 69.5033)
  arc A3 centre (81.5735, 71.5) radius 1.75 clockwise from (82.3802, 69.947) to (82.3802, 73.053)
  arc A4 centre (82.6107, 73.4967) radius 0.5 clockwise from (83.1107, 73.4967) to (82.3802, 73.053)
  arc A5 centre (-82.6107, 73.4967) radius 0.5 clockwise from (-82.3802, 73.053) to (-83.1107, 73.4967)
  arc A6 centre (-81.5735, 71.5) radius 1.75 clockwise from (-82.3802, 73.053) to (-82.3802, 69.947)
  arc A7 centre (-82.6107, 69.5033) radius 0.5 clockwise from (-83.1107, 69.5033) to (-82.3802, 69.947)
  arc A8 centre (-82.6107, -41.5033) radius 0.5 clockwise from (-82.3802, -41.947) to (-83.1107, -41.5033)
  arc A9 centre (-81.5735, -43.5) radius 1.75 clockwise from (-82.3802, -41.947) to (-82.3802, -45.053)
  arc A10 centre (-82.6107, -45.4967) radius 0.5 clockwise from (-83.1107, -45.4967) to (-82.3802, -45.053)
  arc A11 centre (82.6107, -45.4967) radius 0.5 clockwise from (82.3802, -45.053) to (83.1107, -45.4967)
  arc A12 centre (81.5735, -43.5) radius 1.75 clockwise from (82.3802, -45.053) to (82.3802, -41.947)
  circle C9 centre (-36, 53) radius 1.875
  circle C10 centre (36, 53) radius 1.875
  circle C11 centre (36, -25) radius 1.725
  circle C12 centre (-36, -25) radius 1.725
  circle C13 centre (-20, -9) radius 19.5
  circle C14 centre (20, -9) radius 19.5
  arc A13 centre (-20, 35) radius 12.5 clockwise from (-30.2413, 27.833) to (-30.2413, 42.167)
  arc A14 centre (20, 35) radius 12.5 clockwise from (30.2413, 42.167) to (30.2413, 27.833)
  arc A15 centre (20, 35) radius 12.5 clockwise from (20, 47.5) to (20, 22.5)
  arc A16 centre (-20, 35) radius 12.5 clockwise from (-20, 22.5) to (-20, 47.5)
  point P51 (20, -9)
  point P62 (20, -9)
  point P63 (20, 10.5)
  point P64 (-20, 10.5)
  point P50 (-20, -9)
  point P65 (-20, -9)
  point P66 (-20, -28.5)
  point P67 (20, -28.5)
  point P57 (20, 35)
  point P73 (20, 35)
  point P54 (-20, 35)
  point P72 (-20, 35)
  coincident P51 P62
  coincident C14 P63
  vertical L11
  coincident C13 P64
  tangent C13 L12
  coincident P50 P65
  coincident C13 P66
  perpendicular L12 L13
  coincident C14 P67
  tangent C14 L14
  tangent L15 A15
  tangent A15 L16
  parallel L15 L16
  tangent L16 A16
  tangent L15 A16
  coincident P57 P73
  horizontal L17
  coincident P54 P72
extrude "Estrusione1" cut sketch "Schizzo2" profile of C9 C10 C11 C12 C13 C14 A13 A14 L9 L10 L12 L14 L15 A15 L16 A16 against normal blind 36.794
sketch "Schizzo6" plane through (-153.8, 0, 0) normal (-1, 0, 0) x axis (0, -1, 0)
  line L1 (20, 10.5) -> (-20, 10.5)
  line L2 (-20, -28.5) -> (20, -28.5)
  line L3 (-20, 22.5) -> (20, 22.5)
  line L4 (20, 47.5) -> (-20, 47.5)
  line L5 (-83.1107, -63.5) -> (-83.1107, -45.4967)
  curve K1 (-65, -81.6107) -> (-83.1107, -63.5)
  line L6 (65, -81.6107) -> (-65, -81.6107)
  curve K2 (83.1107, -63.5) -> (65, -81.6107)
  line L7 (83.1107, -45.4967) -> (83.1107, -63.5)
  line L8 (83.1107, 69.5033) -> (83.1107, -41.5033)
  line L9 (83.1107, 91.5) -> (83.1107, 73.4967)
  curve K3 (65, 109.6107) -> (83.1107, 91.5)
  line L10 (-65, 109.6107) -> (65, 109.6107)
  curve K4 (-83.1107, 91.5) -> (-65, 109.6107)
  line L11 (-83.1107, 73.4967) -> (-83.1107, 91.5)
  line L12 (-83.1107, -41.5033) -> (-83.1107, 69.5033)
  line L13 (83.6107, -63.5) -> (83.6107, 91.5)
  curve K5 (65, -82.1107) -> (83.6107, -63.5)
  line L14 (-65, -82.1107) -> (65, -82.1107)
  curve K6 (-83.6107, -63.5) -> (-65, -82.1107)
  line L15 (-83.6107, 91.5) -> (-83.6107, -63.5)
  curve K7 (-65, 110.1107) -> (-83.6107, 91.5)
  line L16 (65, 110.1107) -> (-65, 110.1107)
  curve K8 (83.6107, 91.5) -> (65, 110.1107)
  line L17 (65, 111.7507) -> (-65, 111.7507)
  curve K9 (-65, 111.7507) -> (-85.2507, 91.5)
  line L18 (-85.2507, 91.5) -> (-85.2507, -63.5)
  curve K10 (-85.2507, -63.5) -> (-65, -83.7507)
  line L19 (-65, -83.7507) -> (65, -83.7507)
  curve K11 (65, -83.7507) -> (85.2507, -63.5)
  line L20 (85.2507, -63.5) -> (85.2507, 91.5)
  curve K12 (85.2507, 91.5) -> (65, 111.7507)
  line L21 (84.9507, -63.5) -> (84.9507, 91.5)
  curve K13 (65, -83.4507) -> (84.9507, -63.5)
  line L22 (-65, -83.4507) -> (65, -83.4507)
  curve K14 (-84.9507, -63.5) -> (-65, -83.4507)
  line L23 (-84.9507, 91.5) -> (-84.9507, -63.5)
  curve K15 (-65, 111.4507) -> (-84.9507, 91.5)
  line L24 (65, 111.4507) -> (-65, 111.4507)
  curve K16 (84.9507, 91.5) -> (65, 111.4507)
  line L25 (77.2507, -63.5) -> (77.2507, 91.5)
  curve K17 (65, -75.7507) -> (77.2507, -63.5)
  line L26 (-65, -75.7507) -> (65, -75.7507)
  curve K18 (-77.2507, -63.5) -> (-65, -75.7507)
  line L27 (-77.2507, 91.5) -> (-77.2507, -63.5)
  curve K19 (-65, 103.7507) -> (-77.2507, 91.5)
  line L28 (65, 103.7507) -> (-65, 103.7507)
  curve K20 (77.2507, 91.5) -> (65, 103.7507)
  circle C1 centre (-36, 53) radius 1.875
  arc A1 centre (-20, -9) radius 19.5 clockwise from (-20, -28.5) to (-20, 10.5)
  arc A2 centre (20, -9) radius 19.5 clockwise from (20, 10.5) to (20, -28.5)
  circle C2 centre (-36, -25) radius 1.725
  circle C3 centre (36, 53) radius 1.875
  arc A3 centre (-20, 35) radius 12.5 clockwise from (-20, 22.5) to (-20, 47.5)
  arc A4 centre (20, 35) radius 12.5 clockwise from (20, 47.5) to (20, 22.5)
  circle C4 centre (36, -25) radius 1.725
  circle C5 centre (44.1, -78.7) radius 1.75
  circle C6 centre (-44.1, -78.7) radius 1.75
  circle C7 centre (0, -78.7) radius 1.75
  circle C8 centre (44.1, 106.7) radius 1.75
  circle C9 centre (80.2, 14) radius 1.75
  circle C10 centre (-44.1, 106.7) radius 1.75
  circle C11 centre (0, 106.7) radius 1.75
  circle C12 centre (-80.2, 14) radius 1.75
  arc A5 centre (-82.6107, -41.5033) radius 0.5 clockwise from (-82.3802, -41.947) to (-83.1107, -41.5033)
  arc A6 centre (-81.5735, -43.5) radius 1.75 clockwise from (-82.3802, -41.947) to (-82.3802, -45.053)
  arc A7 centre (-82.6107, -45.4967) radius 0.5 clockwise from (-83.1107, -45.4967) to (-82.3802, -45.053)
  arc A8 centre (82.6107, -45.4967) radius 0.5 clockwise from (82.3802, -45.053) to (83.1107, -45.4967)
  arc A9 centre (81.5735, -43.5) radius 1.75 clockwise from (82.3802, -45.053) to (82.3802, -41.947)
  arc A10 centre (82.6107, -41.5033) radius 0.5 clockwise from (83.1107, -41.5033) to (82.3802, -41.947)
  arc A11 centre (82.6107, 69.5033) radius 0.5 clockwise from (82.3802, 69.947) to (83.1107, 69.5033)
  arc A12 centre (81.5735, 71.5) radius 1.75 clockwise from (82.3802, 69.947) to (82.3802, 73.053)
  arc A13 centre (82.6107, 73.4967) radius 0.5 clockwise from (83.1107, 73.4967) to (82.3802, 73.053)
  arc A14 centre (-82.6107, 73.4967) radius 0.5 clockwise from (-82.3802, 73.053) to (-83.1107, 73.4967)
  arc A15 centre (-81.5735, 71.5) radius 1.75 clockwise from (-82.3802, 73.053) to (-82.3802, 69.947)
  arc A16 centre (-82.6107, 69.5033) radius 0.5 clockwise from (-83.1107, 69.5033) to (-82.3802, 69.947)
  dimension "d1004" = 0.3
  dimension "d1005" = 8
extrude "Estrusione6" new body sketch "Schizzo6" profile of C5 C6 C7 C8 C9 C10 C11 C12 A5 A6 A7 L5 K1 L6 K2 L7 A8 A9 A10 L8 A11 A12 A13 L9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 along normal blind 3
component_from_bodies "Corpo->Comp3"
thread "Filettatura1"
